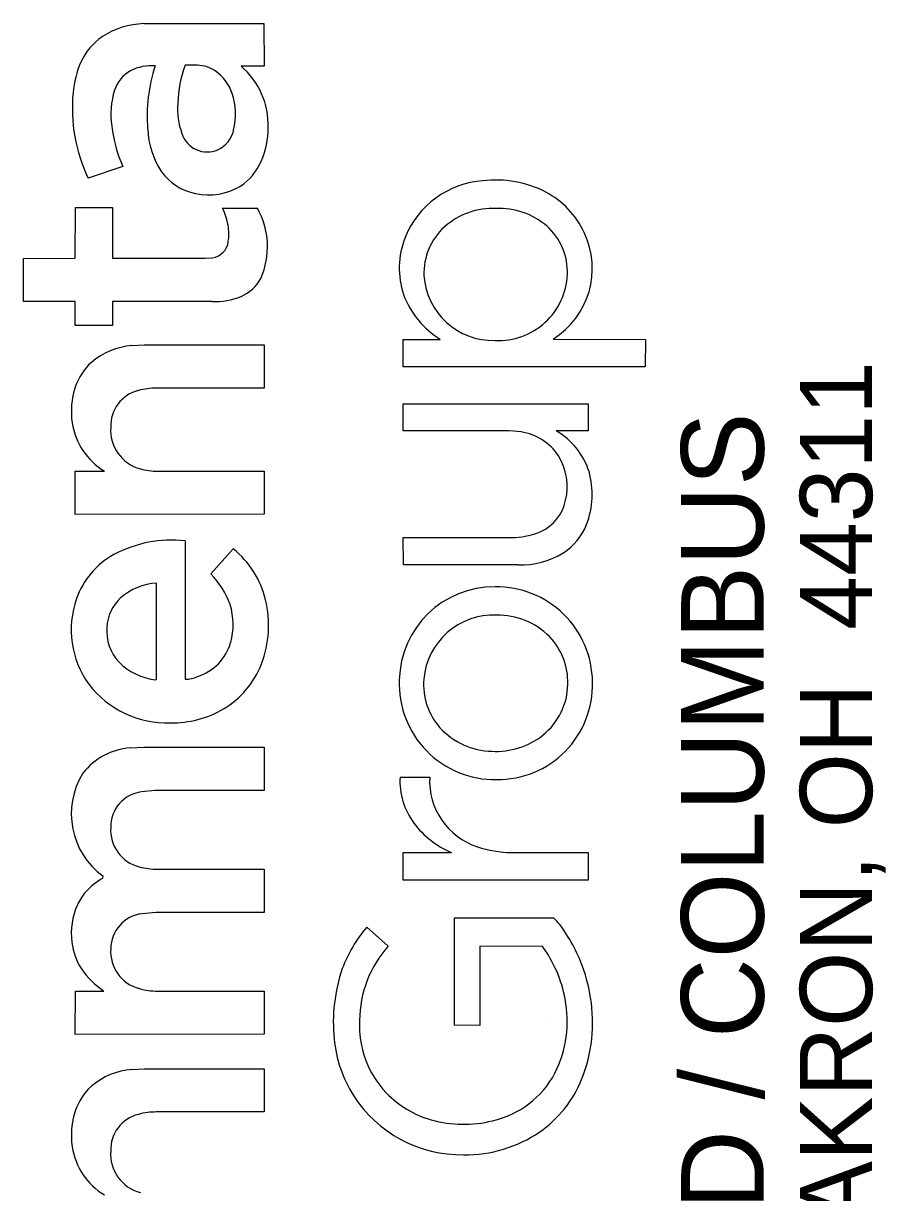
# Model space of a CAD drawing. Extents: x -13.5 to 34, y 0 to 22.
# Drawn here: x 32.39 to 32.984, y 3.882 to 4.689 of the extents above; entities that cross this region are included whole.
import ezdxf

# ---------------------------------------------------------------- set-up
doc = ezdxf.new("R2010")
doc.units = 0
doc.layers.add('RW_X_CL_100_Bearings', color=7, linetype='Continuous')

msp = doc.modelspace()

# ---------------------------------------------------------------- linework, layer by layer
at = {"layer": 'RW_X_CL_100_Bearings'}
for p, q in [((32.47265, 4.68899), (32.55553, 4.68918)), ((32.55553, 4.68918), (32.55571, 4.65956)), ((32.55571, 4.65956), (32.53971, 4.65956)), ((32.45818, 4.59045), (32.43431, 4.58233)), ((32.42542, 4.52705), (32.42548, 4.56209)), ((32.42548, 4.56209), (32.45108, 4.56209)), ((32.45108, 4.56209), (32.45117, 4.52705)), ((32.52695, 4.56159), (32.5511, 4.56159)), ((32.38964, 4.52701), (32.42542, 4.52705)), ((32.38964, 4.49719), (32.38964, 4.52701)), ((32.45117, 4.52705), (32.51498, 4.52705)), ((32.51498, 4.52705), (32.52005, 4.52749)), ((32.42542, 4.49717), (32.38964, 4.49719)), ((32.42542, 4.48067), (32.42542, 4.49717)), ((32.51969, 4.49718), (32.45108, 4.49715)), ((32.45108, 4.49715), (32.45108, 4.48066)), ((32.45108, 4.48066), (32.42542, 4.48067)), ((32.65152, 4.47113), (32.67709, 4.47115)), ((32.65152, 4.45215), (32.65152, 4.47113)), ((32.75491, 4.47132), (32.81858, 4.47108)), ((32.81858, 4.47108), (32.81843, 4.45215)), ((32.46439, 4.46686), (32.47289, 4.46732)), ((32.47289, 4.46732), (32.55571, 4.46732)), ((32.55571, 4.46732), (32.55571, 4.43753)), ((32.81843, 4.45215), (32.65152, 4.45215)), ((32.55571, 4.43753), (32.4814, 4.43746)), ((32.65152, 4.40801), (32.65153, 4.42672)), ((32.65153, 4.42672), (32.7791, 4.42664)), ((32.7791, 4.42664), (32.77908, 4.40796)), ((32.7249, 4.40796), (32.65152, 4.40801)), ((32.7328, 4.40727), (32.7249, 4.40796)), ((32.77908, 4.40796), (32.75689, 4.40796)), ((32.42542, 4.38016), (32.44552, 4.38021)), ((32.42542, 4.35035), (32.42542, 4.38016)), ((32.48222, 4.38021), (32.55569, 4.38021)), ((32.55569, 4.38021), (32.55571, 4.35045)), ((32.55571, 4.35045), (32.42542, 4.35035)), ((32.65154, 4.33443), (32.72905, 4.3345)), ((32.65165, 4.31543), (32.65154, 4.33443)), ((32.50108, 4.33209), (32.50118, 4.23657)), ((32.51882, 4.30927), (32.53422, 4.32662)), ((32.73073, 4.31543), (32.65165, 4.31543)), ((32.48144, 4.23644), (32.48144, 4.30296)), ((32.48016, 4.23628), (32.48144, 4.23644)), ((32.46329, 4.18915), (32.47259, 4.18968)), ((32.47259, 4.18968), (32.55557, 4.18968)), ((32.55557, 4.18968), (32.55571, 4.15982)), ((32.64932, 4.16907), (32.66978, 4.16907)), ((32.48058, 4.15981), (32.47102, 4.15881)), ((32.55571, 4.15982), (32.48058, 4.15981)), ((32.65152, 4.11699), (32.68476, 4.117)), ((32.65152, 4.098), (32.65152, 4.11699)), ((32.72605, 4.11703), (32.7791, 4.11696)), ((32.7791, 4.11696), (32.77903, 4.098)), ((32.44443, 4.09922), (32.44455, 4.10072)), ((32.48218, 4.10553), (32.55571, 4.10548)), ((32.55571, 4.10548), (32.55571, 4.07568)), ((32.77903, 4.098), (32.65152, 4.098)), ((32.4809, 4.07567), (32.47143, 4.07474)), ((32.55571, 4.07568), (32.4809, 4.07567)), ((32.6868, 4.07185), (32.75516, 4.07192)), ((32.6868, 3.99778), (32.6868, 4.07185)), ((32.62636, 4.06548), (32.64114, 4.05241)), ((32.70448, 4.05241), (32.70432, 3.99775)), ((32.74737, 4.05227), (32.70448, 4.05241)), ((32.42542, 3.99152), (32.42545, 4.02138)), ((32.42545, 4.02138), (32.44515, 4.02138)), ((32.48206, 4.02138), (32.55571, 4.02136)), ((32.55571, 4.02136), (32.55571, 3.99156)), ((32.70432, 3.99775), (32.6868, 3.99778)), ((32.75, 4), (32.75, 4)), ((32.55571, 3.99156), (32.42542, 3.99152)), ((32.46439, 3.96736), (32.47289, 3.96783)), ((32.47289, 3.96783), (32.55571, 3.96783)), ((32.55571, 3.96783), (32.55571, 3.93804)), ((32.55571, 3.93804), (32.4814, 3.93796))]:
    msp.add_line(p, q, dxfattribs=at)
for points in [[(32.47265, 4.68899), (32.55553, 4.68918), (32.55571, 4.65956)], [(32.55571, 4.65956), (32.53971, 4.65956)], [(32.45818, 4.59045), (32.43431, 4.58233)], [(32.51969, 4.49718), (32.45108, 4.49715), (32.45108, 4.48066), (32.42542, 4.48067), (32.42542, 4.49717), (32.38964, 4.49719), (32.38964, 4.52701), (32.42542, 4.52705), (32.42548, 4.56209), (32.45108, 4.56209), (32.45117, 4.52705), (32.51498, 4.52705), (32.52005, 4.52749)], [(32.52695, 4.56159), (32.5511, 4.56159)], [(32.75491, 4.47132), (32.81858, 4.47108), (32.81843, 4.45215), (32.65152, 4.45215)], [(32.65152, 4.45215), (32.65152, 4.47113), (32.67709, 4.47115)], [(32.46439, 4.46686), (32.47289, 4.46732), (32.55571, 4.46732), (32.55571, 4.43753), (32.4814, 4.43746)], [(32.7328, 4.40727), (32.7249, 4.40796), (32.65152, 4.40801), (32.65153, 4.42672), (32.7791, 4.42664), (32.77908, 4.40796), (32.75689, 4.40796)], [(32.42542, 4.35035), (32.42542, 4.38016), (32.44552, 4.38021)], [(32.48222, 4.38021), (32.55569, 4.38021), (32.55571, 4.35045), (32.42542, 4.35035)], [(32.73073, 4.31543), (32.65165, 4.31543), (32.65154, 4.33443), (32.72905, 4.3345)], [(32.50108, 4.33209), (32.50118, 4.23657)], [(32.51882, 4.30927), (32.53422, 4.32662)], [(32.48016, 4.23628), (32.48144, 4.23644), (32.48144, 4.30296)], [(32.46329, 4.18915), (32.47259, 4.18968), (32.55557, 4.18968), (32.55571, 4.15982), (32.48058, 4.15981), (32.47102, 4.15881)], [(32.64932, 4.16907), (32.66978, 4.16907)], [(32.72605, 4.11703), (32.7791, 4.11696), (32.77903, 4.098), (32.65152, 4.098)], [(32.65152, 4.098), (32.65152, 4.11699), (32.68476, 4.117)], [(32.44443, 4.09922), (32.44455, 4.10072)], [(32.48218, 4.10553), (32.55571, 4.10548), (32.55571, 4.07568), (32.4809, 4.07567), (32.47143, 4.07474)], [(32.74737, 4.05227), (32.70448, 4.05241), (32.70432, 3.99775), (32.6868, 3.99778), (32.6868, 4.07185), (32.75516, 4.07192)], [(32.62636, 4.06548), (32.64114, 4.05241)], [(32.42542, 3.99152), (32.42545, 4.02138), (32.44515, 4.02138)], [(32.48206, 4.02138), (32.55571, 4.02136), (32.55571, 3.99156), (32.42542, 3.99152)], [(32.46439, 3.96736), (32.47289, 3.96783), (32.55571, 3.96783), (32.55571, 3.93804), (32.4814, 3.93796)]]:
    msp.add_lwpolyline(points, dxfattribs=at)
for centre, radius, start, end in [((32.47452, 4.63256), 0.05646, 91.89422, 122.63175), ((32.47452, 4.63256), 0.05646, 91.89422, 122.63175), ((32.46847, 4.64467), 0.04302, 124.53704, 155.65938), ((32.46847, 4.64467), 0.04302, 124.53704, 155.65938), ((32.48824, 4.63612), 0.06457, 155.9764, 175.31491), ((32.48824, 4.63612), 0.06457, 155.9764, 175.31491), ((32.47525, 4.6356), 0.024, 119.42515, 161.66285), ((32.47525, 4.6356), 0.024, 119.42515, 161.66285), ((32.47786, 4.62778), 0.03213, 85.38017, 116.62224), ((32.47786, 4.62778), 0.03213, 85.38017, 116.62224), ((32.58787, 4.62508), 0.1129, 162.08213, 184.52847), ((32.58787, 4.62508), 0.1129, 162.08213, 184.52847), ((32.58013, 4.63131), 0.08411, 159.83657, 178.03621), ((32.58013, 4.63131), 0.08411, 159.83657, 178.03621), ((32.50509, 4.60743), 0.05302, 79.66963, 94.23216), ((32.50509, 4.60743), 0.05302, 79.66963, 94.23216), ((32.50892, 4.63643), 0.02384, 56.89129, 76.21489), ((32.50892, 4.63643), 0.02384, 56.89129, 76.21489), ((32.5052, 4.63184), 0.02973, 17.59837, 55.72819), ((32.5052, 4.63184), 0.02973, 17.59837, 55.72819), ((32.50551, 4.61914), 0.05295, 358.07459, 49.76196), ((32.50551, 4.61914), 0.05295, 358.07459, 49.76196), ((32.53639, 4.63078), 0.113, 174.61011, 205.38987), ((32.53639, 4.63078), 0.113, 174.61011, 205.38987), ((32.50758, 4.62645), 0.05758, 163.13694, 188.16749), ((32.50758, 4.62645), 0.05758, 163.13694, 188.16749), ((32.4916, 4.6264), 0.04435, 345.94084, 18.99188), ((32.4916, 4.6264), 0.04435, 345.94084, 18.99188), ((32.54655, 4.6303), 0.05063, 175.59026, 199.88569), ((32.54655, 4.6303), 0.05063, 175.59026, 199.88569), ((32.54725, 4.62973), 0.09735, 186.75982, 203.79807), ((32.54725, 4.62973), 0.09735, 186.75982, 203.79807), ((32.53279, 4.61874), 0.05752, 182.56764, 213.71437), ((32.53279, 4.61874), 0.05752, 182.56764, 213.71437), ((32.51521, 4.61994), 0.01989, 295.28829, 347.46387), ((32.51521, 4.61994), 0.01989, 295.28829, 347.46387), ((32.50187, 4.61678), 0.05657, 336.01604, 0.59505), ((32.50187, 4.61678), 0.05657, 336.01604, 0.59505), ((32.51642, 4.61886), 0.01841, 198.28436, 293.30806), ((32.51642, 4.61886), 0.01841, 198.28436, 293.30806), ((32.51752, 4.60969), 0.03938, 303.44357, 336.18), ((32.51752, 4.60969), 0.03938, 303.44357, 336.18), ((32.51487, 4.60782), 0.03656, 215.06685, 259.81327), ((32.51487, 4.60782), 0.03656, 215.06685, 259.81327), ((32.51753, 4.6131), 0.04227, 257.52557, 300.88195), ((32.51753, 4.6131), 0.04227, 257.52557, 300.88195), ((32.71081, 4.51825), 0.06243, 93.98662, 158.31194), ((32.71081, 4.51825), 0.06243, 93.98662, 158.31194), ((32.71557, 4.5065), 0.07459, 62.68889, 97.01346), ((32.71557, 4.5065), 0.07459, 62.68889, 97.01346), ((32.72123, 4.51914), 0.06076, 25.06574, 61.96022), ((32.72123, 4.51914), 0.06076, 25.06574, 61.96022), ((32.48625, 4.54199), 0.04518, 10.15449, 25.72303), ((32.48625, 4.54199), 0.04518, 10.15449, 25.72303), ((32.50302, 4.53506), 0.05491, 336.58903, 28.89913), ((32.50302, 4.53506), 0.05491, 336.58903, 28.89913), ((32.71379, 4.51017), 0.05134, 87.89653, 131.18123), ((32.71379, 4.51017), 0.05134, 87.89653, 131.18123), ((32.7175, 4.51023), 0.05127, 49.90886, 92.03625), ((32.7175, 4.51023), 0.05127, 49.90886, 92.03625), ((32.49573, 4.54365), 0.03556, 351.91398, 10.20594), ((32.49573, 4.54365), 0.03556, 351.91398, 10.20594), ((32.7092, 4.51674), 0.04338, 132.32887, 182.09489), ((32.7092, 4.51674), 0.04338, 132.32887, 182.09489), ((32.72154, 4.51733), 0.04327, 358.04871, 47.94467), ((32.72154, 4.51733), 0.04327, 358.04871, 47.94467), ((32.7245, 4.52004), 0.05743, 301.97764, 25.64176), ((32.7245, 4.52004), 0.05743, 301.97764, 25.64176), ((32.51837, 4.54001), 0.01263, 277.61423, 353.79181), ((32.51837, 4.54001), 0.01263, 277.61423, 353.79181), ((32.70695, 4.52016), 0.05815, 158.65601, 198.17101), ((32.70695, 4.52016), 0.05815, 158.65601, 198.17101), ((32.52913, 4.52612), 0.02749, 292.68889, 332.05977), ((32.52913, 4.52612), 0.02749, 292.68889, 332.05977), ((32.71352, 4.51815), 0.04776, 183.59741, 271.7045), ((32.71352, 4.51815), 0.04776, 183.59741, 271.7045), ((32.71717, 4.51801), 0.04766, 267.31494, 357.4019), ((32.71717, 4.51801), 0.04766, 267.31494, 357.4019), ((32.52088, 4.54856), 0.05139, 268.67266, 291.52354), ((32.52088, 4.54856), 0.05139, 268.67266, 291.52354), ((32.7103, 4.52433), 0.0627, 200.83985, 238.01619), ((32.7103, 4.52433), 0.0627, 200.83985, 238.01619), ((32.46871, 4.41716), 0.04988, 94.97056, 130.22484), ((32.46871, 4.41716), 0.04988, 94.97056, 130.22484), ((32.46348, 4.42551), 0.04016, 132.22383, 161.68229), ((32.46348, 4.42551), 0.04016, 132.22383, 161.68229), ((32.47872, 4.42108), 0.05602, 162.27398, 187.79173), ((32.47872, 4.42108), 0.05602, 162.27398, 187.79173), ((32.47482, 4.41155), 0.02498, 103.68683, 182.21395), ((32.47482, 4.41155), 0.02498, 103.68683, 182.21395), ((32.48108, 4.39145), 0.04601, 89.60515, 105.33026), ((32.48108, 4.39145), 0.04601, 89.60515, 105.33026), ((32.47027, 4.4209), 0.04763, 188.96462, 238.69865), ((32.47027, 4.4209), 0.04763, 188.96462, 238.69865), ((32.47735, 4.40846), 0.02757, 175.58441, 255.13816), ((32.47735, 4.40846), 0.02757, 175.58441, 255.13816), ((32.72711, 4.36998), 0.03772, 33.50082, 81.32954), ((32.72711, 4.36998), 0.03772, 33.50082, 81.32954), ((32.73239, 4.36485), 0.04959, 17.62209, 60.38974), ((32.73239, 4.36485), 0.04959, 17.62209, 60.38974), ((32.72414, 4.3695), 0.04048, 346.56179, 31.75389), ((32.72414, 4.3695), 0.04048, 346.56179, 31.75389), ((32.48183, 4.42235), 0.04215, 254.08913, 270.52838), ((32.48183, 4.42235), 0.04215, 254.08913, 270.52838), ((32.72343, 4.36415), 0.05838, 339.16197, 15.61485), ((32.72343, 4.36415), 0.05838, 339.16197, 15.61485), ((32.73371, 4.36616), 0.03042, 294.63214, 348.48625), ((32.73371, 4.36616), 0.03042, 294.63214, 348.48625), ((32.739, 4.35901), 0.04201, 303.10391, 338.15613), ((32.739, 4.35901), 0.04201, 303.10391, 338.15613), ((32.72747, 4.38081), 0.04633, 271.95199, 294.08943), ((32.72747, 4.38081), 0.04633, 271.95199, 294.08943), ((32.49176, 4.24874), 0.08387, 83.62118, 118.28448), ((32.49176, 4.24874), 0.08387, 83.62118, 118.28448), ((32.49399, 4.2763), 0.06443, 13.53275, 51.36266), ((32.49399, 4.2763), 0.06443, 13.53275, 51.36266), ((32.47894, 4.27368), 0.05583, 118.82935, 160.62242), ((32.47894, 4.27368), 0.05583, 118.82935, 160.62242), ((32.7321, 4.37256), 0.05715, 268.62699, 301.47779), ((32.7321, 4.37256), 0.05715, 268.62699, 301.47779), ((32.48033, 4.27018), 0.05485, 19.0387, 45.44322), ((32.48033, 4.27018), 0.05485, 19.0387, 45.44322), ((32.4844, 4.26071), 0.04236, 94.01311, 130.88062), ((32.4844, 4.26071), 0.04236, 94.01311, 130.88062), ((32.47703, 4.2709), 0.02985, 132.98553, 177.1802), ((32.47703, 4.2709), 0.02985, 132.98553, 177.1802), ((32.71435, 4.23484), 0.06552, 89.48213, 178.77752), ((32.71435, 4.23484), 0.06552, 89.48213, 178.77752), ((32.71582, 4.23414), 0.06623, 0.42265, 90.7613), ((32.71582, 4.23414), 0.06623, 0.42265, 90.7613), ((32.48697, 4.27074), 0.06438, 160.52138, 215.78155), ((32.48697, 4.27074), 0.06438, 160.52138, 215.78155), ((32.48724, 4.27433), 0.04701, 344.60723, 17.00675), ((32.48724, 4.27433), 0.04701, 344.60723, 17.00675), ((32.48289, 4.27384), 0.0758, 339.35431, 13.37708), ((32.48289, 4.27384), 0.0758, 339.35431, 13.37708), ((32.71397, 4.23244), 0.04846, 87.68827, 175.01696), ((32.71397, 4.23244), 0.04846, 87.68827, 175.01696), ((32.71659, 4.23036), 0.05052, 44.91202, 90.75914), ((32.71659, 4.23036), 0.05052, 44.91202, 90.75914), ((32.47824, 4.26966), 0.03114, 175.00138, 223.2876), ((32.47824, 4.26966), 0.03114, 175.00138, 223.2876), ((32.49895, 4.27177), 0.03504, 288.01084, 343.55364), ((32.49895, 4.27177), 0.03504, 288.01084, 343.55364), ((32.71955, 4.23452), 0.04549, 358.32279, 43.83486), ((32.71955, 4.23452), 0.04549, 358.32279, 43.83486), ((32.48546, 4.27826), 0.04232, 225.06454, 262.79701), ((32.48546, 4.27826), 0.04232, 225.06454, 262.79701), ((32.49548, 4.26982), 0.0626, 300.94393, 338.73223), ((32.49548, 4.26982), 0.0626, 300.94393, 338.73223), ((32.50129, 4.25678), 0.02021, 269.70042, 294.87295), ((32.50129, 4.25678), 0.02021, 269.70042, 294.87295), ((32.71483, 4.2334), 0.06606, 177.53728, 270.94524), ((32.71483, 4.2334), 0.06606, 177.53728, 270.94524), ((32.71085, 4.23311), 0.0453, 175.51467, 221.42047), ((32.71085, 4.23311), 0.0453, 175.51467, 221.42047), ((32.48908, 4.27516), 0.06872, 217.74341, 271.65606), ((32.48908, 4.27516), 0.06872, 217.74341, 271.65606), ((32.71671, 4.23271), 0.06536, 269.30834, 1.67905), ((32.71671, 4.23271), 0.06536, 269.30834, 1.67905), ((32.71931, 4.23374), 0.04572, 308.90382, 359.30947), ((32.71931, 4.23374), 0.04572, 308.90382, 359.30947), ((32.49204, 4.27702), 0.07055, 269.20529, 300.33566), ((32.49204, 4.27702), 0.07055, 269.20529, 300.33566), ((32.71399, 4.23734), 0.05046, 222.66255, 268.37331), ((32.71399, 4.23734), 0.05046, 222.66255, 268.37331), ((32.71567, 4.23859), 0.05178, 266.55312, 308.67253), ((32.71567, 4.23859), 0.05178, 266.55312, 308.67253), ((32.46638, 4.14404), 0.04521, 93.91118, 142.30723), ((32.46638, 4.14404), 0.04521, 93.91118, 142.30723), ((32.47585, 4.14373), 0.05319, 148.28793, 233.9556), ((32.47585, 4.14373), 0.05319, 148.28793, 233.9556), ((32.69878, 4.16662), 0.04952, 177.16211, 216.28024), ((32.69878, 4.16662), 0.04952, 177.16211, 216.28024), ((32.71735, 4.16638), 0.04764, 176.76988, 252.15044), ((32.71735, 4.16638), 0.04764, 176.76988, 252.15044), ((32.47384, 4.13499), 0.02399, 96.75763, 181.6251), ((32.47384, 4.13499), 0.02399, 96.75763, 181.6251), ((32.47577, 4.13241), 0.02597, 175.81573, 256.16716), ((32.47577, 4.13241), 0.02597, 175.81573, 256.16716), ((32.70975, 4.17555), 0.06366, 216.91526, 246.88619), ((32.70975, 4.17555), 0.06366, 216.91526, 246.88619), ((32.7269, 4.19175), 0.07473, 251.13884, 269.34694), ((32.7269, 4.19175), 0.07473, 251.13884, 269.34694), ((32.4817, 4.15053), 0.04501, 254.34629, 270.61033), ((32.4817, 4.15053), 0.04501, 254.34629, 270.61033), ((32.4638, 4.06267), 0.04137, 117.91625, 139.24296), ((32.4638, 4.06267), 0.04137, 117.91625, 139.24296), ((32.46194, 4.06452), 0.03875, 139.52447, 154.84698), ((32.46194, 4.06452), 0.03875, 139.52447, 154.84698), ((32.47144, 4.0612), 0.04877, 156.06382, 187.3493), ((32.47144, 4.0612), 0.04877, 156.06382, 187.3493), ((32.47421, 4.05056), 0.02434, 96.5532, 179.94902), ((32.47421, 4.05056), 0.02434, 96.5532, 179.94902), ((32.72498, 4.03937), 0.04438, 30.98913, 47.16099), ((32.72498, 4.03937), 0.04438, 30.98913, 47.16099), ((32.70163, 4.00187), 0.09855, 139.79476, 159.13696), ((32.70163, 4.00187), 0.09855, 139.79476, 159.13696), ((32.67091, 4.00018), 0.11106, 25.30315, 33.96179), ((32.67091, 4.00018), 0.11106, 25.30315, 33.96179), ((32.46461, 4.05974), 0.04181, 186.5579, 213.38846), ((32.46461, 4.05974), 0.04181, 186.5579, 213.38846), ((32.47608, 4.04863), 0.02628, 175.722, 255.78627), ((32.47608, 4.04863), 0.02628, 175.722, 255.78627), ((32.69899, 4.00079), 0.07753, 138.25804, 179.70064), ((32.69899, 4.00079), 0.07753, 138.25804, 179.70064), ((32.67889, 4.00099), 0.08556, 10.07509, 36.83189), ((32.67889, 4.00099), 0.08556, 10.07509, 36.83189), ((32.6704, 3.99987), 0.11166, 8.80339, 25.33484), ((32.6704, 3.99987), 0.11166, 8.80339, 25.33484), ((32.47886, 4.07078), 0.0598, 214.70433, 235.68724), ((32.47886, 4.07078), 0.0598, 214.70433, 235.68724), ((32.7187, 3.99968), 0.11536, 161.14379, 185.62812), ((32.7187, 3.99968), 0.11536, 161.14379, 185.62812), ((32.48195, 4.06518), 0.0438, 253.66719, 270.14979), ((32.48195, 4.06518), 0.0438, 253.66719, 270.14979), ((32.68425, 4.00057), 0.08036, 333.46689, 11.03668), ((32.68425, 4.00057), 0.08036, 333.46689, 11.03668), ((32.67564, 3.99977), 0.10649, 338.28866, 9.28548), ((32.67564, 3.99977), 0.10649, 338.28866, 9.28548), ((32.68811, 3.99732), 0.06676, 176.66577, 223.6912), ((32.68811, 3.99732), 0.06676, 176.66577, 223.6912), ((32.69336, 3.99699), 0.08987, 185.50773, 212.01294), ((32.69336, 3.99699), 0.08987, 185.50773, 212.01294), ((32.46871, 3.91767), 0.04988, 94.97056, 130.22484), ((32.46871, 3.91767), 0.04988, 94.97056, 130.22484), ((32.69868, 3.99547), 0.0652, 282.88151, 331.81475), ((32.69868, 3.99547), 0.0652, 282.88151, 331.81475), ((32.46348, 3.92602), 0.04016, 132.22383, 161.68229), ((32.46348, 3.92602), 0.04016, 132.22383, 161.68229), ((32.69835, 3.99168), 0.08241, 305.03061, 337.67573), ((32.69835, 3.99168), 0.08241, 305.03061, 337.67573), ((32.69211, 3.99748), 0.08908, 212.70222, 270.71399), ((32.69211, 3.99748), 0.08908, 212.70222, 270.71399), ((32.69045, 4.00011), 0.07039, 224.02147, 253.88), ((32.69045, 4.00011), 0.07039, 224.02147, 253.88), ((32.47872, 3.92158), 0.05602, 162.27398, 187.79173), ((32.47872, 3.92158), 0.05602, 162.27398, 187.79173), ((32.48108, 3.89196), 0.04601, 89.60515, 105.33026), ((32.48108, 3.89196), 0.04601, 89.60515, 105.33026), ((32.47482, 3.91206), 0.02498, 103.68683, 182.21395), ((32.47482, 3.91206), 0.02498, 103.68683, 182.21395), ((32.69318, 4.01254), 0.08309, 254.45353, 283.9512), ((32.69318, 4.01254), 0.08309, 254.45353, 283.9512), ((32.69429, 3.99979), 0.09138, 269.3273, 304.19632), ((32.69429, 3.99979), 0.09138, 269.3273, 304.19632), ((32.47027, 3.92141), 0.04763, 188.96462, 238.69865), ((32.47027, 3.92141), 0.04763, 188.96462, 238.69865), ((32.47735, 3.90897), 0.02757, 175.58441, 255.13816), ((32.47735, 3.90897), 0.02757, 175.58441, 255.13816)]:
    msp.add_arc(centre, radius, start, end, dxfattribs=at)

# ---------------------------------------------------------------- texts
for s, height, p in [('450 GRANT ST., AKRON, OH  44311', 0.0498462, (32.97489, 3.33738)), ('AKRON / CLEVELAND / COLUMBUS', 0.056969, (32.90012, 3.138))]:
    msp.add_text(s, height=height, rotation=90, dxfattribs=at).set_placement(p)

doc.saveas('drawing.dxf')
